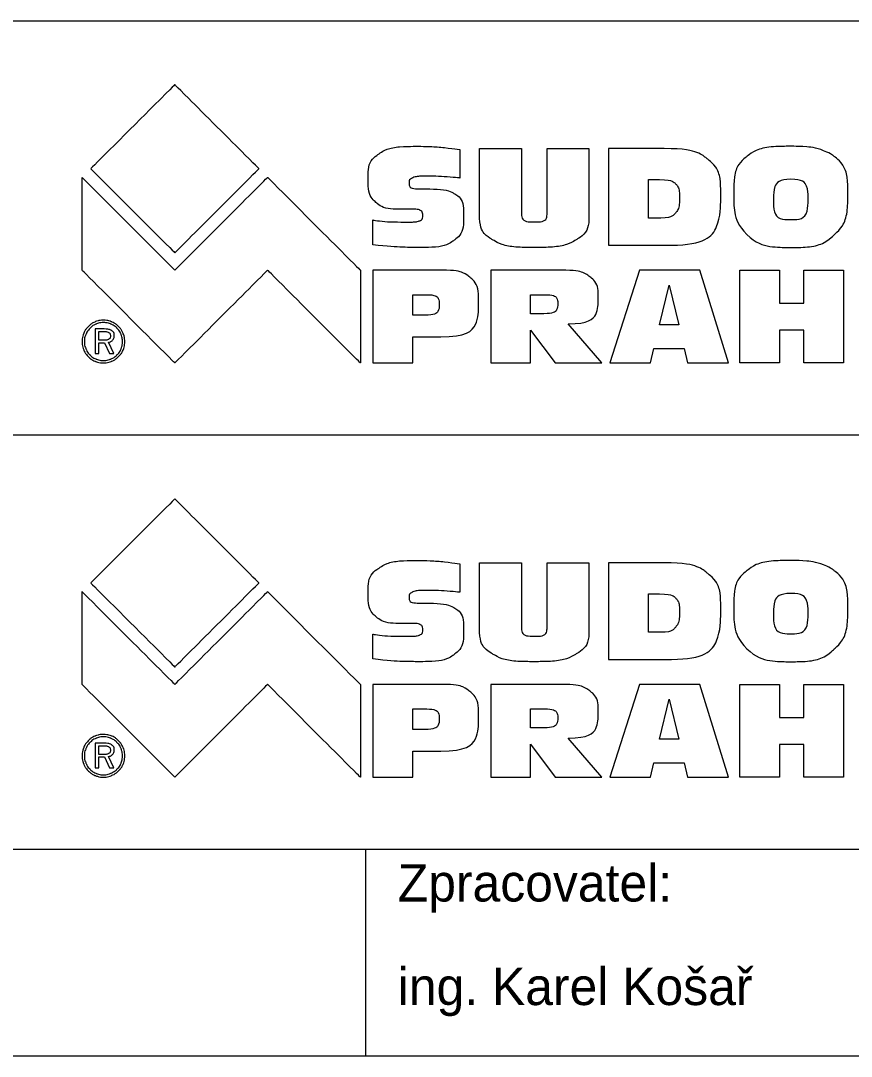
# Model space of a CAD drawing. Extents: x 142 to 352, y -2116 to -1819.
# Drawn here: x 281.1 to 323.2, y -2020.4 to -1967.9 of the extents above; entities that cross this region are included whole.
import ezdxf

# ---------------------------------------------------------------- set-up
doc = ezdxf.new("R2010")
doc.units = 0
for name, color, linetype in [('Rozpiska - logo SUDOP PRAHA', 7, 'Continuous'), ('Rozpiska_pole_6', 7, 'Continuous'), ('Rozpiska_pole_7', 7, 'Continuous')]:
    doc.layers.add(name, color=color, linetype=linetype)

msp = doc.modelspace()

# ---------------------------------------------------------------- linework, layer by layer
at = {"layer": 'Rozpiska - logo SUDOP PRAHA'}
for points in [[(313.698, -1974.382), (310.874, -1974.382), (310.874, -1979.273), (314.076, -1979.273)], [(313.523, -1977.902), (312.901, -1977.902), (312.901, -1975.954), (313.454, -1975.954)], [(302.448, -1980.542), (298.929, -1980.542), (298.929, -1985.245), (300.962, -1985.245), (300.962, -1983.924), (302.367, -1983.924)], [(308.481, -1980.542), (304.902, -1980.542), (304.902, -1985.245), (306.926, -1985.245), (306.926, -1983.578), (308.172, -1985.245), (310.545, -1985.245), (308.837, -1983.262)], [(312.997, -1985.245), (313.175, -1984.512), (314.712, -1984.512), (314.883, -1985.245), (316.964, -1985.245), (315.513, -1980.542), (312.453, -1980.542), (310.945, -1985.245), (312.997, -1985.245)], [(313.951, -1981.295), (314.44, -1983.317), (313.454, -1983.317), (313.951, -1981.295)], [(301.564, -1982.826), (300.962, -1982.826), (300.962, -1981.786), (301.666, -1981.786)], [(307.601, -1982.748), (306.926, -1982.748), (306.926, -1981.786), (307.627, -1981.786)], [(285.299, -1983.523), (284.843, -1983.523), (284.843, -1984.768), (285.03, -1984.768), (285.03, -1984.221), (285.321, -1984.221), (285.584, -1984.768), (285.798, -1984.768), (285.52, -1984.194)], [(285.264, -1984.097), (285.03, -1984.097), (285.03, -1983.65), (285.264, -1983.65)], [(313.698, -1995.382), (310.874, -1995.382), (310.874, -2000.273), (314.076, -2000.273)], [(313.523, -1998.902), (312.901, -1998.902), (312.901, -1996.954), (313.454, -1996.954)], [(302.448, -2001.542), (298.929, -2001.542), (298.929, -2006.245), (300.962, -2006.245), (300.962, -2004.924), (302.367, -2004.924)], [(308.481, -2001.542), (304.902, -2001.542), (304.902, -2006.245), (306.926, -2006.245), (306.926, -2004.578), (308.172, -2006.245), (310.545, -2006.245), (308.837, -2004.262)], [(312.997, -2006.245), (313.175, -2005.512), (314.712, -2005.512), (314.883, -2006.245), (316.964, -2006.245), (315.513, -2001.542), (312.453, -2001.542), (310.945, -2006.245), (312.997, -2006.245)], [(313.951, -2002.295), (314.44, -2004.317), (313.454, -2004.317), (313.951, -2002.295)], [(301.564, -2003.826), (300.962, -2003.826), (300.962, -2002.786), (301.666, -2002.786)], [(307.601, -2003.748), (306.926, -2003.748), (306.926, -2002.786), (307.627, -2002.786)], [(285.299, -2004.523), (284.843, -2004.523), (284.843, -2005.768), (285.03, -2005.768), (285.03, -2005.221), (285.321, -2005.221), (285.584, -2005.768), (285.798, -2005.768), (285.52, -2005.194)], [(285.264, -2005.097), (285.03, -2005.097), (285.03, -2004.65), (285.264, -2004.65)]]:
    msp.add_lwpolyline(points, dxfattribs=at)
for points in [[(284.627, -1975.399), (284.627, -1975.399), (288.889, -1971.137), (288.889, -1971.137), (288.889, -1971.137), (288.889, -1971.137), (293.151, -1975.399), (293.151, -1975.399), (293.151, -1975.399), (293.151, -1975.399), (288.889, -1979.66), (288.889, -1979.66), (288.889, -1979.66), (288.889, -1979.66), (284.627, -1975.399), (284.627, -1975.399)], [(298.929, -1979.253), (299.694, -1979.344), (300.496, -1979.39), (301.336, -1979.39), (301.336, -1979.39), (302.141, -1979.39), (302.707, -1979.272), (303.035, -1979.036), (303.035, -1979.036), (303.365, -1978.799), (303.531, -1978.391), (303.531, -1977.811), (303.531, -1977.811), (303.531, -1977.244), (303.382, -1976.866), (303.084, -1976.677), (303.084, -1976.677), (302.804, -1976.507), (302.235, -1976.422), (301.378, -1976.422), (301.378, -1976.422), (300.966, -1976.422), (300.761, -1976.325), (300.761, -1976.131), (300.761, -1976.131), (300.761, -1976.008), (300.821, -1975.919), (300.942, -1975.864), (300.942, -1975.864), (301.066, -1975.808), (301.282, -1975.78), (301.59, -1975.78), (301.59, -1975.78), (302.112, -1975.78), (302.684, -1975.81), (303.335, -1975.87), (303.335, -1975.87), (303.335, -1975.87), (303.335, -1974.428), (303.335, -1974.428), (303.335, -1974.428), (302.558, -1974.319), (301.832, -1974.264), (301.128, -1974.264), (301.128, -1974.264), (300.242, -1974.264), (299.614, -1974.39), (299.243, -1974.642), (299.243, -1974.642), (298.872, -1974.892), (298.687, -1975.292), (298.687, -1975.84), (298.687, -1975.84), (298.687, -1976.449), (298.819, -1976.871), (299.084, -1977.105), (299.084, -1977.105), (299.352, -1977.339), (299.796, -1977.454), (300.416, -1977.45), (300.416, -1977.45), (300.416, -1977.45), (300.935, -1977.45), (300.935, -1977.45), (300.935, -1977.45), (301.116, -1977.45), (301.249, -1977.47), (301.332, -1977.51), (301.332, -1977.51), (301.415, -1977.55), (301.457, -1977.637), (301.457, -1977.771), (301.457, -1977.771), (301.457, -1977.911), (301.403, -1978.002), (301.294, -1978.042), (301.294, -1978.042), (301.188, -1978.082), (301.009, -1978.102), (300.757, -1978.102), (300.757, -1978.102), (299.975, -1978.102), (299.366, -1978.068), (298.929, -1977.998), (298.929, -1977.998), (298.929, -1977.998), (298.929, -1979.253), (298.929, -1979.253)], [(304.337, -1977.707), (304.337, -1978.308), (304.558, -1978.74), (304.998, -1979.001), (304.998, -1979.001), (305.438, -1979.261), (306.136, -1979.39), (307.091, -1979.39), (307.091, -1979.39), (308.086, -1979.39), (308.8, -1979.261), (309.233, -1979.001), (309.233, -1979.001), (309.669, -1978.742), (309.886, -1978.304), (309.886, -1977.687), (309.886, -1977.687), (309.886, -1977.687), (309.886, -1974.382), (309.886, -1974.382), (309.886, -1974.382), (309.886, -1974.382), (307.759, -1974.382), (307.759, -1974.382), (307.759, -1974.382), (307.759, -1974.382), (307.759, -1977.62), (307.759, -1977.62), (307.759, -1977.62), (307.759, -1977.94), (307.547, -1978.1), (307.121, -1978.1), (307.121, -1978.1), (306.684, -1978.1), (306.465, -1977.935), (306.465, -1977.607), (306.465, -1977.607), (306.465, -1977.607), (306.465, -1974.382), (306.465, -1974.382), (306.465, -1974.382), (306.465, -1974.382), (304.337, -1974.382), (304.337, -1974.382), (304.337, -1974.382), (304.337, -1974.382), (304.337, -1977.707), (304.337, -1977.707)], [(314.076, -1979.273), (315.735, -1979.273), (316.564, -1978.407), (316.564, -1976.676), (316.564, -1976.676), (316.564, -1975.865), (316.346, -1975.281), (315.908, -1974.923), (315.908, -1974.923), (315.47, -1974.562), (314.734, -1974.382), (313.698, -1974.382)], [(321.937, -1974.552), (321.501, -1974.36), (320.9, -1974.264), (320.136, -1974.264), (320.136, -1974.264), (319.065, -1974.264), (318.311, -1974.441), (317.876, -1974.793), (317.876, -1974.793), (317.44, -1975.143), (317.223, -1975.768), (317.223, -1976.667), (317.223, -1976.667), (317.223, -1977.603), (317.444, -1978.292), (317.887, -1978.731)], [(317.887, -1978.731), (318.33, -1979.17), (319.072, -1979.39), (320.113, -1979.39), (320.113, -1979.39), (321.113, -1979.39), (321.845, -1979.179), (322.308, -1978.758), (322.308, -1978.758), (322.774, -1978.336), (323.007, -1977.639), (323.007, -1976.667), (323.007, -1976.667), (323.007, -1975.792), (322.791, -1975.173), (322.361, -1974.81), (322.361, -1974.81), (322.243, -1974.71), (322.102, -1974.624), (321.937, -1974.552)], [(284.186, -1980.542), (284.186, -1980.542), (288.889, -1985.245), (288.889, -1985.245), (288.889, -1985.245), (288.889, -1985.245), (293.592, -1980.542), (293.592, -1980.542), (293.592, -1980.542), (293.592, -1980.542), (298.294, -1985.245), (298.294, -1985.245), (298.294, -1985.245), (298.294, -1985.245), (298.294, -1980.542), (298.294, -1980.542), (298.294, -1980.542), (298.294, -1980.542), (293.592, -1975.839), (293.592, -1975.839), (293.592, -1975.839), (293.592, -1975.839), (288.889, -1980.542), (288.889, -1980.542), (288.889, -1980.542), (288.889, -1980.542), (284.186, -1975.839), (284.186, -1975.839), (284.186, -1975.839), (284.186, -1975.839), (284.186, -1980.542), (284.186, -1980.542)], [(313.454, -1975.954), (313.869, -1975.954), (314.142, -1976.023), (314.274, -1976.162), (314.274, -1976.162), (314.407, -1976.299), (314.473, -1976.532), (314.473, -1976.861), (314.473, -1976.861), (314.473, -1977.217), (314.404, -1977.48), (314.267, -1977.65), (314.267, -1977.65), (314.132, -1977.818), (313.884, -1977.902), (313.523, -1977.902)], [(320.12, -1975.93), (320.7, -1975.93), (320.99, -1976.255), (320.99, -1976.904), (320.99, -1976.904), (320.99, -1977.618), (320.7, -1977.975), (320.12, -1977.975), (320.12, -1977.975), (319.533, -1977.975), (319.239, -1977.635), (319.239, -1976.954), (319.239, -1976.954), (319.239, -1976.272), (319.533, -1975.93), (320.12, -1975.93)], [(302.367, -1983.924), (303.649, -1983.924), (304.29, -1983.347), (304.29, -1982.193), (304.29, -1982.193), (304.29, -1981.575), (304.143, -1981.145), (303.849, -1980.904), (303.849, -1980.904), (303.557, -1980.663), (303.09, -1980.542), (302.448, -1980.542)], [(308.837, -1983.262), (309.85, -1983.262), (310.356, -1982.819), (310.356, -1981.934), (310.356, -1981.934), (310.356, -1981.45), (310.213, -1981.097), (309.927, -1980.875), (309.927, -1980.875), (309.641, -1980.653), (309.159, -1980.542), (308.481, -1980.542)], [(317.528, -1985.245), (317.528, -1985.245), (319.547, -1985.245), (319.547, -1985.245), (319.547, -1985.245), (319.547, -1985.245), (319.547, -1983.581), (319.547, -1983.581), (319.547, -1983.581), (319.547, -1983.581), (320.776, -1983.581), (320.776, -1983.581), (320.776, -1983.581), (320.776, -1983.581), (320.776, -1985.245), (320.776, -1985.245), (320.776, -1985.245), (320.776, -1985.245), (322.795, -1985.245), (322.795, -1985.245), (322.795, -1985.245), (322.795, -1985.245), (322.795, -1980.542), (322.795, -1980.542), (322.795, -1980.542), (322.795, -1980.542), (320.776, -1980.542), (320.776, -1980.542), (320.776, -1980.542), (320.776, -1980.542), (320.776, -1982.215), (320.776, -1982.215), (320.776, -1982.215), (320.776, -1982.215), (319.547, -1982.215), (319.547, -1982.215), (319.547, -1982.215), (319.547, -1982.215), (319.547, -1980.542), (319.547, -1980.542), (319.547, -1980.542), (319.547, -1980.542), (317.528, -1980.542), (317.528, -1980.542), (317.528, -1980.542), (317.528, -1980.542), (317.528, -1985.245), (317.528, -1985.245)], [(301.666, -1981.786), (302.082, -1981.786), (302.29, -1981.956), (302.29, -1982.296), (302.29, -1982.296), (302.29, -1982.649), (302.048, -1982.826), (301.564, -1982.826)], [(307.627, -1981.786), (308.075, -1981.786), (308.299, -1981.933), (308.299, -1982.228), (308.299, -1982.228), (308.299, -1982.575), (308.067, -1982.748), (307.601, -1982.748)], [(285.267, -1983.082), (285.12, -1983.082), (284.982, -1983.108), (284.853, -1983.161), (284.853, -1983.161), (284.724, -1983.215), (284.61, -1983.292), (284.51, -1983.393), (284.51, -1983.393), (284.406, -1983.498), (284.326, -1983.617), (284.27, -1983.751), (284.27, -1983.751), (284.214, -1983.884), (284.186, -1984.021), (284.186, -1984.163), (284.186, -1984.163), (284.186, -1984.307), (284.214, -1984.444), (284.268, -1984.575), (284.268, -1984.575), (284.322, -1984.706), (284.401, -1984.822), (284.504, -1984.924), (284.504, -1984.924), (284.607, -1985.029), (284.723, -1985.108), (284.854, -1985.163), (284.854, -1985.163), (284.913, -1985.188), (284.973, -1985.207), (285.035, -1985.22)], [(286.232, -1984.167), (286.232, -1984.301), (286.209, -1984.423), (286.162, -1984.537), (286.162, -1984.537), (286.115, -1984.65), (286.046, -1984.751), (285.957, -1984.838), (285.957, -1984.838), (285.862, -1984.931), (285.756, -1985.001), (285.637, -1985.05), (285.637, -1985.05), (285.518, -1985.099), (285.395, -1985.124), (285.267, -1985.124), (285.267, -1985.124), (285.14, -1985.124), (285.018, -1985.1), (284.902, -1985.051), (284.902, -1985.051), (284.785, -1985.003), (284.681, -1984.933), (284.588, -1984.841), (284.588, -1984.841), (284.497, -1984.749), (284.427, -1984.645), (284.378, -1984.529), (284.378, -1984.529), (284.329, -1984.413), (284.304, -1984.291), (284.304, -1984.165), (284.304, -1984.165), (284.304, -1984.038), (284.329, -1983.916), (284.379, -1983.798), (284.379, -1983.798), (284.429, -1983.681), (284.501, -1983.575), (284.594, -1983.479), (284.594, -1983.479), (284.685, -1983.389), (284.788, -1983.32), (284.902, -1983.273), (284.902, -1983.273), (285.017, -1983.226), (285.139, -1983.202), (285.267, -1983.202), (285.267, -1983.202), (285.398, -1983.202), (285.524, -1983.226), (285.641, -1983.276), (285.641, -1983.276), (285.759, -1983.324), (285.864, -1983.394), (285.957, -1983.485), (285.957, -1983.485), (286.046, -1983.575), (286.114, -1983.678), (286.161, -1983.795), (286.161, -1983.795), (286.208, -1983.912), (286.232, -1984.036), (286.232, -1984.167)], [(285.035, -1985.22), (285.11, -1985.237), (285.187, -1985.245), (285.267, -1985.245), (285.267, -1985.245), (285.409, -1985.245), (285.547, -1985.217), (285.68, -1985.161), (285.68, -1985.161), (285.814, -1985.106), (285.933, -1985.026), (286.038, -1984.921), (286.038, -1984.921), (286.14, -1984.821), (286.218, -1984.707), (286.271, -1984.578), (286.271, -1984.578), (286.323, -1984.449), (286.35, -1984.31), (286.35, -1984.163), (286.35, -1984.163), (286.35, -1984.016), (286.323, -1983.878), (286.269, -1983.746), (286.269, -1983.746), (286.215, -1983.615), (286.138, -1983.499), (286.038, -1983.399), (286.038, -1983.399), (285.937, -1983.296), (285.82, -1983.217), (285.688, -1983.163), (285.688, -1983.163), (285.557, -1983.109), (285.416, -1983.082), (285.267, -1983.082)], [(285.264, -1983.65), (285.389, -1983.65), (285.481, -1983.668), (285.537, -1983.704), (285.537, -1983.704), (285.593, -1983.739), (285.621, -1983.798), (285.621, -1983.88), (285.621, -1983.88), (285.621, -1983.958), (285.594, -1984.014), (285.541, -1984.048), (285.541, -1984.048), (285.488, -1984.08), (285.395, -1984.097), (285.264, -1984.097)], [(285.52, -1984.194), (285.61, -1984.182), (285.681, -1984.146), (285.735, -1984.087), (285.735, -1984.087), (285.788, -1984.027), (285.814, -1983.954), (285.814, -1983.867), (285.814, -1983.867), (285.814, -1983.749), (285.773, -1983.663), (285.688, -1983.607), (285.688, -1983.607), (285.604, -1983.551), (285.474, -1983.523), (285.299, -1983.523)], [(284.627, -1996.399), (284.627, -1996.399), (288.889, -1992.137), (288.889, -1992.137), (288.889, -1992.137), (288.889, -1992.137), (293.151, -1996.399), (293.151, -1996.399), (293.151, -1996.399), (293.151, -1996.399), (288.889, -2000.66), (288.889, -2000.66), (288.889, -2000.66), (288.889, -2000.66), (284.627, -1996.399), (284.627, -1996.399)], [(298.929, -2000.253), (299.694, -2000.344), (300.496, -2000.39), (301.336, -2000.39), (301.336, -2000.39), (302.141, -2000.39), (302.707, -2000.272), (303.035, -2000.036), (303.035, -2000.036), (303.365, -1999.799), (303.531, -1999.391), (303.531, -1998.811), (303.531, -1998.811), (303.531, -1998.244), (303.382, -1997.866), (303.084, -1997.677), (303.084, -1997.677), (302.804, -1997.507), (302.235, -1997.422), (301.378, -1997.422), (301.378, -1997.422), (300.966, -1997.422), (300.761, -1997.325), (300.761, -1997.131), (300.761, -1997.131), (300.761, -1997.008), (300.821, -1996.919), (300.942, -1996.864), (300.942, -1996.864), (301.066, -1996.808), (301.282, -1996.78), (301.59, -1996.78), (301.59, -1996.78), (302.112, -1996.78), (302.684, -1996.81), (303.335, -1996.87), (303.335, -1996.87), (303.335, -1996.87), (303.335, -1995.428), (303.335, -1995.428), (303.335, -1995.428), (302.558, -1995.319), (301.832, -1995.264), (301.128, -1995.264), (301.128, -1995.264), (300.242, -1995.264), (299.614, -1995.39), (299.243, -1995.642), (299.243, -1995.642), (298.872, -1995.892), (298.687, -1996.292), (298.687, -1996.84), (298.687, -1996.84), (298.687, -1997.449), (298.819, -1997.871), (299.084, -1998.105), (299.084, -1998.105), (299.352, -1998.339), (299.796, -1998.454), (300.416, -1998.45), (300.416, -1998.45), (300.416, -1998.45), (300.935, -1998.45), (300.935, -1998.45), (300.935, -1998.45), (301.116, -1998.45), (301.249, -1998.47), (301.332, -1998.51), (301.332, -1998.51), (301.415, -1998.55), (301.457, -1998.637), (301.457, -1998.771), (301.457, -1998.771), (301.457, -1998.911), (301.403, -1999.002), (301.294, -1999.042), (301.294, -1999.042), (301.188, -1999.082), (301.009, -1999.102), (300.757, -1999.102), (300.757, -1999.102), (299.975, -1999.102), (299.366, -1999.068), (298.929, -1998.998), (298.929, -1998.998), (298.929, -1998.998), (298.929, -2000.253), (298.929, -2000.253)], [(304.337, -1998.707), (304.337, -1999.308), (304.558, -1999.74), (304.998, -2000.001), (304.998, -2000.001), (305.438, -2000.261), (306.136, -2000.39), (307.091, -2000.39), (307.091, -2000.39), (308.086, -2000.39), (308.8, -2000.261), (309.233, -2000.001), (309.233, -2000.001), (309.669, -1999.742), (309.886, -1999.304), (309.886, -1998.687), (309.886, -1998.687), (309.886, -1998.687), (309.886, -1995.382), (309.886, -1995.382), (309.886, -1995.382), (309.886, -1995.382), (307.759, -1995.382), (307.759, -1995.382), (307.759, -1995.382), (307.759, -1995.382), (307.759, -1998.62), (307.759, -1998.62), (307.759, -1998.62), (307.759, -1998.94), (307.547, -1999.1), (307.121, -1999.1), (307.121, -1999.1), (306.684, -1999.1), (306.465, -1998.935), (306.465, -1998.607), (306.465, -1998.607), (306.465, -1998.607), (306.465, -1995.382), (306.465, -1995.382), (306.465, -1995.382), (306.465, -1995.382), (304.337, -1995.382), (304.337, -1995.382), (304.337, -1995.382), (304.337, -1995.382), (304.337, -1998.707), (304.337, -1998.707)], [(314.076, -2000.273), (315.735, -2000.273), (316.564, -1999.407), (316.564, -1997.676), (316.564, -1997.676), (316.564, -1996.865), (316.346, -1996.281), (315.908, -1995.923), (315.908, -1995.923), (315.47, -1995.562), (314.734, -1995.382), (313.698, -1995.382)], [(321.937, -1995.552), (321.501, -1995.36), (320.9, -1995.264), (320.136, -1995.264), (320.136, -1995.264), (319.065, -1995.264), (318.311, -1995.441), (317.876, -1995.793), (317.876, -1995.793), (317.44, -1996.143), (317.223, -1996.768), (317.223, -1997.667), (317.223, -1997.667), (317.223, -1998.603), (317.444, -1999.292), (317.887, -1999.731)], [(317.887, -1999.731), (318.33, -2000.17), (319.072, -2000.39), (320.113, -2000.39), (320.113, -2000.39), (321.113, -2000.39), (321.845, -2000.179), (322.308, -1999.758), (322.308, -1999.758), (322.774, -1999.336), (323.007, -1998.639), (323.007, -1997.667), (323.007, -1997.667), (323.007, -1996.792), (322.791, -1996.173), (322.361, -1995.81), (322.361, -1995.81), (322.243, -1995.71), (322.102, -1995.624), (321.937, -1995.552)], [(284.186, -2001.542), (284.186, -2001.542), (288.889, -2006.245), (288.889, -2006.245), (288.889, -2006.245), (288.889, -2006.245), (293.592, -2001.542), (293.592, -2001.542), (293.592, -2001.542), (293.592, -2001.542), (298.294, -2006.245), (298.294, -2006.245), (298.294, -2006.245), (298.294, -2006.245), (298.294, -2001.542), (298.294, -2001.542), (298.294, -2001.542), (298.294, -2001.542), (293.592, -1996.839), (293.592, -1996.839), (293.592, -1996.839), (293.592, -1996.839), (288.889, -2001.542), (288.889, -2001.542), (288.889, -2001.542), (288.889, -2001.542), (284.186, -1996.839), (284.186, -1996.839), (284.186, -1996.839), (284.186, -1996.839), (284.186, -2001.542), (284.186, -2001.542)], [(313.454, -1996.954), (313.869, -1996.954), (314.142, -1997.023), (314.274, -1997.162), (314.274, -1997.162), (314.407, -1997.299), (314.473, -1997.532), (314.473, -1997.861), (314.473, -1997.861), (314.473, -1998.217), (314.404, -1998.48), (314.267, -1998.65), (314.267, -1998.65), (314.132, -1998.818), (313.884, -1998.902), (313.523, -1998.902)], [(320.12, -1996.93), (320.7, -1996.93), (320.99, -1997.255), (320.99, -1997.904), (320.99, -1997.904), (320.99, -1998.618), (320.7, -1998.975), (320.12, -1998.975), (320.12, -1998.975), (319.533, -1998.975), (319.239, -1998.635), (319.239, -1997.954), (319.239, -1997.954), (319.239, -1997.272), (319.533, -1996.93), (320.12, -1996.93)], [(302.367, -2004.924), (303.649, -2004.924), (304.29, -2004.347), (304.29, -2003.193), (304.29, -2003.193), (304.29, -2002.575), (304.143, -2002.145), (303.849, -2001.904), (303.849, -2001.904), (303.557, -2001.663), (303.09, -2001.542), (302.448, -2001.542)], [(308.837, -2004.262), (309.85, -2004.262), (310.356, -2003.819), (310.356, -2002.934), (310.356, -2002.934), (310.356, -2002.45), (310.213, -2002.097), (309.927, -2001.875), (309.927, -2001.875), (309.641, -2001.653), (309.159, -2001.542), (308.481, -2001.542)], [(317.528, -2006.245), (317.528, -2006.245), (319.547, -2006.245), (319.547, -2006.245), (319.547, -2006.245), (319.547, -2006.245), (319.547, -2004.581), (319.547, -2004.581), (319.547, -2004.581), (319.547, -2004.581), (320.776, -2004.581), (320.776, -2004.581), (320.776, -2004.581), (320.776, -2004.581), (320.776, -2006.245), (320.776, -2006.245), (320.776, -2006.245), (320.776, -2006.245), (322.795, -2006.245), (322.795, -2006.245), (322.795, -2006.245), (322.795, -2006.245), (322.795, -2001.542), (322.795, -2001.542), (322.795, -2001.542), (322.795, -2001.542), (320.776, -2001.542), (320.776, -2001.542), (320.776, -2001.542), (320.776, -2001.542), (320.776, -2003.215), (320.776, -2003.215), (320.776, -2003.215), (320.776, -2003.215), (319.547, -2003.215), (319.547, -2003.215), (319.547, -2003.215), (319.547, -2003.215), (319.547, -2001.542), (319.547, -2001.542), (319.547, -2001.542), (319.547, -2001.542), (317.528, -2001.542), (317.528, -2001.542), (317.528, -2001.542), (317.528, -2001.542), (317.528, -2006.245), (317.528, -2006.245)], [(301.666, -2002.786), (302.082, -2002.786), (302.29, -2002.956), (302.29, -2003.296), (302.29, -2003.296), (302.29, -2003.649), (302.048, -2003.826), (301.564, -2003.826)], [(307.627, -2002.786), (308.075, -2002.786), (308.299, -2002.933), (308.299, -2003.228), (308.299, -2003.228), (308.299, -2003.575), (308.067, -2003.748), (307.601, -2003.748)], [(285.267, -2004.082), (285.12, -2004.082), (284.982, -2004.108), (284.853, -2004.161), (284.853, -2004.161), (284.724, -2004.215), (284.61, -2004.292), (284.51, -2004.393), (284.51, -2004.393), (284.406, -2004.498), (284.326, -2004.617), (284.27, -2004.751), (284.27, -2004.751), (284.214, -2004.884), (284.186, -2005.021), (284.186, -2005.163), (284.186, -2005.163), (284.186, -2005.307), (284.214, -2005.444), (284.268, -2005.575), (284.268, -2005.575), (284.322, -2005.706), (284.401, -2005.822), (284.504, -2005.924), (284.504, -2005.924), (284.607, -2006.029), (284.723, -2006.108), (284.854, -2006.163), (284.854, -2006.163), (284.913, -2006.188), (284.973, -2006.207), (285.035, -2006.22)], [(286.232, -2005.167), (286.232, -2005.301), (286.209, -2005.423), (286.162, -2005.537), (286.162, -2005.537), (286.115, -2005.65), (286.046, -2005.751), (285.957, -2005.838), (285.957, -2005.838), (285.862, -2005.931), (285.756, -2006.001), (285.637, -2006.05), (285.637, -2006.05), (285.518, -2006.099), (285.395, -2006.124), (285.267, -2006.124), (285.267, -2006.124), (285.14, -2006.124), (285.018, -2006.1), (284.902, -2006.051), (284.902, -2006.051), (284.785, -2006.003), (284.681, -2005.933), (284.588, -2005.841), (284.588, -2005.841), (284.497, -2005.749), (284.427, -2005.645), (284.378, -2005.529), (284.378, -2005.529), (284.329, -2005.413), (284.304, -2005.291), (284.304, -2005.165), (284.304, -2005.165), (284.304, -2005.038), (284.329, -2004.916), (284.379, -2004.798), (284.379, -2004.798), (284.429, -2004.681), (284.501, -2004.575), (284.594, -2004.479), (284.594, -2004.479), (284.685, -2004.389), (284.788, -2004.32), (284.902, -2004.273), (284.902, -2004.273), (285.017, -2004.226), (285.139, -2004.202), (285.267, -2004.202), (285.267, -2004.202), (285.398, -2004.202), (285.524, -2004.226), (285.641, -2004.276), (285.641, -2004.276), (285.759, -2004.324), (285.864, -2004.394), (285.957, -2004.485), (285.957, -2004.485), (286.046, -2004.575), (286.114, -2004.678), (286.161, -2004.795), (286.161, -2004.795), (286.208, -2004.912), (286.232, -2005.036), (286.232, -2005.167)], [(285.035, -2006.22), (285.11, -2006.237), (285.187, -2006.245), (285.267, -2006.245), (285.267, -2006.245), (285.409, -2006.245), (285.547, -2006.217), (285.68, -2006.161), (285.68, -2006.161), (285.814, -2006.106), (285.933, -2006.026), (286.038, -2005.921), (286.038, -2005.921), (286.14, -2005.821), (286.218, -2005.707), (286.271, -2005.578), (286.271, -2005.578), (286.323, -2005.449), (286.35, -2005.31), (286.35, -2005.163), (286.35, -2005.163), (286.35, -2005.016), (286.323, -2004.878), (286.269, -2004.746), (286.269, -2004.746), (286.215, -2004.615), (286.138, -2004.499), (286.038, -2004.399), (286.038, -2004.399), (285.937, -2004.296), (285.82, -2004.217), (285.688, -2004.163), (285.688, -2004.163), (285.557, -2004.109), (285.416, -2004.082), (285.267, -2004.082)], [(285.264, -2004.65), (285.389, -2004.65), (285.481, -2004.668), (285.537, -2004.704), (285.537, -2004.704), (285.593, -2004.739), (285.621, -2004.798), (285.621, -2004.88), (285.621, -2004.88), (285.621, -2004.958), (285.594, -2005.014), (285.541, -2005.048), (285.541, -2005.048), (285.488, -2005.08), (285.395, -2005.097), (285.264, -2005.097)], [(285.52, -2005.194), (285.61, -2005.182), (285.681, -2005.146), (285.735, -2005.087), (285.735, -2005.087), (285.788, -2005.027), (285.814, -2004.954), (285.814, -2004.867), (285.814, -2004.867), (285.814, -2004.749), (285.773, -2004.663), (285.688, -2004.607), (285.688, -2004.607), (285.604, -2004.551), (285.474, -2004.523), (285.299, -2004.523)]]:
    msp.add_open_spline(points, degree=3, dxfattribs=at)
at = {"layer": 'Rozpiska_pole_6'}
msp.add_lwpolyline([(161.701, -1967.896), (340.201, -1967.896), (340.201, -2020.396), (161.701, -2020.396)], close=True, dxfattribs=at)
at = {"layer": 'Rozpiska_pole_7'}
for p, q in [((161.701, -1988.896), (340.201, -1988.896)), ((161.701, -2009.896), (340.201, -2009.896)), ((298.569, -2020.396), (298.569, -2009.896))]:
    msp.add_line(p, q, dxfattribs=at)

# ---------------------------------------------------------------- texts
at = {"layer": 'Rozpiska_pole_6'}
for s, p in [('Zpracovatel:', (300.192, -2012.549)), ('ing. Karel Košař', (300.192, -2017.799))]:
    msp.add_text(s, height=1.89, dxfattribs=at).set_placement(p)

doc.saveas('drawing.dxf')
